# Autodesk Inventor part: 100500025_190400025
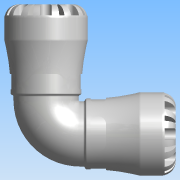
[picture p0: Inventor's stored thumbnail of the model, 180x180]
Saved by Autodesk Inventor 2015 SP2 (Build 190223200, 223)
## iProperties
Created: 2016-12
Part Number: 100500025_190400025
Material: PVC-Piping
Description: PLASSON 90° ELBOW 25X25 SERIES 1
Document SubType Name: Modeling
Designer: KIM
Mass: 664.223 g
Surface Area: 733.008 cm^2
Volume: 474.445 cm^3
Density: 1.4 g/cm^3
Appearance: Smooth - White
Author: KIM
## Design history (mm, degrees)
derived "1005.ipt"
feature "Solid1::1005.ipt"
tag "TaggingFeature1"
body "Solid1"
other parameters: "d1" = 20.16, "d2" = 25, "d3" = 31.25, "d4" = 47, "d8" = 39.95, "d13" = 6.3, "d14" = 6.3, "d15" = 0, "d17" = 360 deg, "d19" = 8 deg, "d20" = 0.5, "d21" = 0.5, "d22" = 8 deg, "d24" = 0, "d26" = 360 deg, "d33" = 4.7, "d43" = 36.66, "d51" = 0.47, "d54" = 8.75, "d55" = 5.5, "d57" = 12.348, "d58" = 0, "d74" = 0, "d77" = 2.08333, "d78" = 48, "d82" = 0.5, "d115" = 360 deg, "d207" = 90 deg, "d228" = 7.4375, "d247" = 0.94, "d248" = 2.88, "d268" = 21.9725, "d269" = 2.88, "d270" = 73, "d272" = 90 deg, "d274" = 0, "d275" = 0, "d_" = 25, "E_" = 47, "l_" = 48, "A_" = 73, "d9" = 7.875, "d11" = 47, "d12" = 31.25
